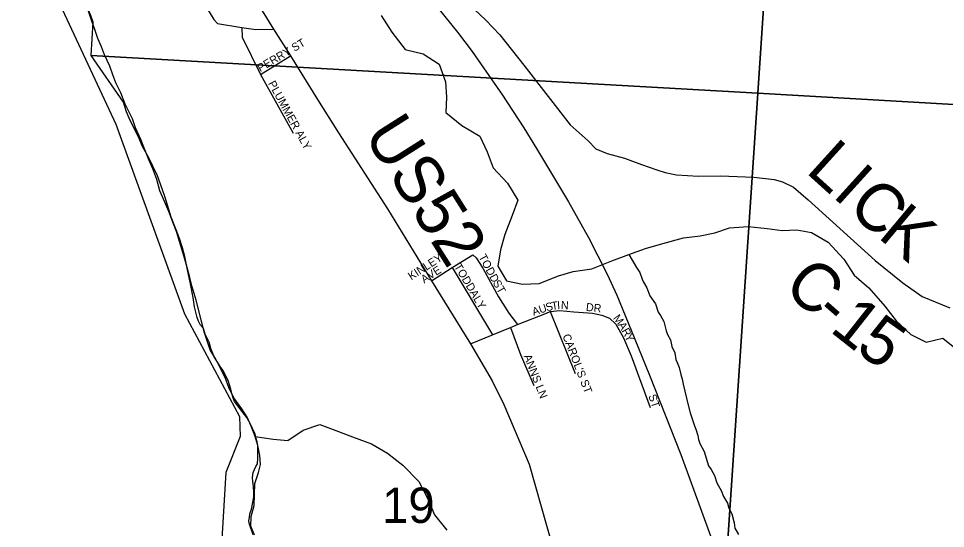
# Model space of a CAD drawing. Extents: x 1949938.81 to 1949945.61, y 152207.65 to 152214.09.
# Drawn here: x 1949939.486 to 1949940.583, y 152211.771 to 152212.375 of the extents above; entities that cross this region are included whole.
import ezdxf

# ---------------------------------------------------------------- set-up
doc = ezdxf.new("R2010")
doc.units = 0
for name, color, linetype in [('GM_X_County', 7, 'Continuous'), ('GM_X_County_Road', 7, 'Continuous'), ('GM_X_County_Road_Text', 7, 'Continuous'), ('GM_X_Major_River', 7, 'Continuous'), ('GM_X_Minor_River', 7, 'Continuous'), ('GM_X_Section', 7, 'Continuous'), ('GM_X_Section_Text', 7, 'Continuous'), ('GM_X_Township', 7, 'Continuous'), ('GM_X_Township_Subdivision', 7, 'Continuous'), ('GM_X_Township_Subdivision_Text', 7, 'Continuous'), ('GM_X_US_Route', 7, 'Continuous')]:
    doc.layers.add(name, color=color, linetype=linetype)

msp = doc.modelspace()

# ---------------------------------------------------------------- linework, layer by layer
at = {"layer": 'GM_X_County'}
msp.add_lwpolyline([(1949938.8069, 152213.1813), (1949938.8908, 152213.14), (1949939.0267, 152213.041), (1949939.1111, 152212.9977), (1949939.166, 152212.9381), (1949939.244, 152212.8721), (1949939.3272, 152212.7909), (1949939.4464, 152212.5807), (1949939.6012, 152212.2498), (1949939.6822, 152212.0255), (1949939.7473, 152211.904), (1949939.7481, 152211.8801), (1949939.7311, 152211.8376), (1949939.7258, 152211.7457)], dxfattribs=at)
at = {"layer": 'GM_X_County_Road'}
for points in [[(1949939.6083, 152212.6496), (1949939.6416, 152212.5985), (1949939.7012, 152212.4996), (1949939.734, 152212.4495), (1949939.7877, 152212.362), (1949939.8079, 152212.3305), (1949939.8398, 152212.2788), (1949939.8646, 152212.2394), (1949939.9224, 152212.1496), (1949939.9746, 152212.0644), (1949940.0209, 152211.9898), (1949940.0463, 152211.946), (1949940.0603, 152211.9182), (1949940.0902, 152211.8474), (1949940.1245, 152211.7264)], [(1949939.9911, 152212.4181), (1949940.0391, 152212.3728), (1949940.0554, 152212.3554), (1949940.084, 152212.3196), (1949940.1389, 152212.2489), (1949940.16, 152212.2301), (1949940.1692, 152212.2206), (1949940.1827, 152212.215), (1949940.2031, 152212.2094), (1949940.2232, 152212.202), (1949940.2415, 152212.1957), (1949940.2514, 152212.1925), (1949940.2645, 152212.19), (1949940.2905, 152212.1882), (1949940.3166, 152212.1886), (1949940.3563, 152212.187), (1949940.3803, 152212.1844), (1949940.39, 152212.1815), (1949940.403, 152212.1752), (1949940.4203, 152212.1604), (1949940.4996, 152212.0883), (1949940.5324, 152212.0621), (1949940.5553, 152212.0457), (1949940.588, 152212.0326)]]:
    msp.add_lwpolyline(points, dxfattribs=at)
at = {"layer": 'GM_X_Major_River'}
for points in [[(1949939.5841, 152212.3413), (1949939.5799, 152212.3512), (1949939.5765, 152212.3607), (1949939.5723, 152212.3728), (1949939.5682, 152212.3846), (1949939.5644, 152212.3971), (1949939.5595, 152212.4115), (1949939.5534, 152212.427), (1949939.5485, 152212.438), (1949939.544, 152212.4483), (1949939.5391, 152212.4589), (1949939.5345, 152212.4699), (1949939.53, 152212.4802), (1949939.5251, 152212.4904), (1949939.5191, 152212.5029), (1949939.5138, 152212.5128), (1949939.5089, 152212.5234), (1949939.5028, 152212.5336), (1949939.4986, 152212.5431), (1949939.4907, 152212.5556), (1949939.4835, 152212.5689)], [(1949939.765, 152211.7635), (1949939.7609, 152211.7741), (1949939.7613, 152211.7855), (1949939.7647, 152211.7988), (1949939.7654, 152211.8246), (1949939.77, 152211.8378), (1949939.7722, 152211.8473), (1949939.7715, 152211.8576), (1949939.7692, 152211.8697), (1949939.7658, 152211.8803), (1949939.7613, 152211.8925), (1949939.7564, 152211.9031), (1949939.7503, 152211.913), (1949939.7409, 152211.9259), (1949939.7348, 152211.9384), (1949939.7303, 152211.9502), (1949939.7246, 152211.9615), (1949939.7193, 152211.9718), (1949939.7129, 152211.9828), (1949939.7095, 152211.9923), (1949939.7061, 152212.0029), (1949939.7023, 152212.0162), (1949939.6997, 152212.0276), (1949939.6963, 152212.0416), (1949939.6914, 152212.0572), (1949939.6887, 152212.0685), (1949939.6853, 152212.0803), (1949939.6827, 152212.0902), (1949939.6797, 152212.1008), (1949939.6766, 152212.111), (1949939.6729, 152212.1228), (1949939.6687, 152212.1338), (1949939.6638, 152212.1463), (1949939.6589, 152212.1573), (1949939.6532, 152212.171), (1949939.6494, 152212.1843), (1949939.6449, 152212.1968), (1949939.6407, 152212.2066), (1949939.6351, 152212.2207), (1949939.6305, 152212.2317), (1949939.6245, 152212.2453), (1949939.6207, 152212.256), (1949939.612, 152212.2734), (1949939.6071, 152212.2867), (1949939.6011, 152212.2988), (1949939.5977, 152212.3083), (1949939.5939, 152212.3182), (1949939.5875, 152212.3318), (1949939.5841, 152212.3413)]]:
    msp.add_lwpolyline(points, dxfattribs=at)
at = {"layer": 'GM_X_Minor_River'}
for points in [[(1949939.9149, 152212.3785), (1949939.9277, 152212.3587), (1949939.9436, 152212.3382), (1949939.9647, 152212.3328), (1949939.9836, 152212.3206), (1949939.9911, 152212.3), (1949939.9925, 152212.2818), (1949939.9917, 152212.2636), (1949940.0106, 152212.2483), (1949940.0317, 152212.2354), (1949940.0407, 152212.2171), (1949940.0475, 152212.1981), (1949940.0648, 152212.1798), (1949940.0769, 152212.16), (1949940.07, 152212.1418), (1949940.0615, 152212.1191), (1949940.0562, 152212.1009), (1949940.0531, 152212.0819), (1949940.0636, 152212.0644), (1949940.0825, 152212.0605), (1949940.1022, 152212.0612), (1949940.125, 152212.0702), (1949940.1424, 152212.0755), (1949940.1644, 152212.0785), (1949940.1879, 152212.0882), (1949940.2084, 152212.0957), (1949940.2281, 152212.1025), (1949940.2486, 152212.1085), (1949940.2728, 152212.1152), (1949940.2925, 152212.1175), (1949940.31, 152212.1212), (1949940.3274, 152212.1272), (1949940.3494, 152212.1286), (1949940.3721, 152212.1263), (1949940.3895, 152212.1239), (1949940.4069, 152212.1246), (1949940.4243, 152212.1215), (1949940.444, 152212.11), (1949940.4628, 152212.0902), (1949940.4749, 152212.0712), (1949940.4922, 152212.056), (1949940.5111, 152212.0346), (1949940.5246, 152212.0171), (1949940.542, 152212.0011), (1949940.5601, 152211.9919), (1949940.5798, 152211.9964), (1949940.5979, 152211.9819)], [(1949940.2084, 152212.0957), (1949940.2173, 152212.08), (1949940.2214, 152212.0742), (1949940.2239, 152212.0662), (1949940.2257, 152212.0628), (1949940.2294, 152212.0563), (1949940.233, 152212.0467), (1949940.2396, 152212.0371), (1949940.2429, 152212.0275), (1949940.2455, 152212.0233), (1949940.2495, 152212.0164), (1949940.2523, 152212.0053), (1949940.2541, 152212.0008), (1949940.2575, 152211.9946), (1949940.2592, 152211.9866), (1949940.2625, 152211.9793), (1949940.2639, 152211.9713), (1949940.2653, 152211.9679), (1949940.2679, 152211.9618), (1949940.2696, 152211.9538), (1949940.2714, 152211.948), (1949940.2724, 152211.9423), (1949940.2763, 152211.9256), (1949940.2774, 152211.9221), (1949940.2809, 152211.9084), (1949940.2824, 152211.9034), (1949940.286, 152211.8927), (1949940.2874, 152211.8889), (1949940.2899, 152211.8816), (1949940.2906, 152211.8767), (1949940.2924, 152211.8721), (1949940.2972, 152211.8625), (1949940.3026, 152211.8457), (1949940.3055, 152211.8411), (1949940.3095, 152211.8342), (1949940.3124, 152211.8254), (1949940.3143, 152211.822), (1949940.3176, 152211.8162), (1949940.3201, 152211.8093), (1949940.3249, 152211.8013), (1949940.3267, 152211.7955), (1949940.33, 152211.7886), (1949940.3328, 152211.778), (1949940.3338, 152211.7719), (1949940.3382, 152211.7642)], [(1949939.7658, 152211.8803), (1949939.7871, 152211.8771), (1949939.8045, 152211.8755), (1949939.8228, 152211.8876), (1949939.8425, 152211.8944), (1949939.8614, 152211.8875), (1949939.881, 152211.8798), (1949939.9037, 152211.8714), (1949939.9226, 152211.8607), (1949939.9407, 152211.8462), (1949939.9596, 152211.8271), (1949939.9701, 152211.8073), (1949939.9784, 152211.7876), (1949939.9927, 152211.7693)]]:
    msp.add_lwpolyline(points, dxfattribs=at)
at = {"layer": 'GM_X_Section'}
for points in [[(1949940.4294, 152213.3146), (1949940.3609, 152212.2864), (1949939.5717, 152212.3312), (1949939.5744, 152212.3703), (1949939.5718, 152212.3771), (1949939.5691, 152212.3839), (1949939.5646, 152212.393), (1949939.5608, 152212.4021), (1949939.5544, 152212.4169), (1949939.5517, 152212.4267), (1949939.5472, 152212.4392), (1949939.5434, 152212.451), (1949939.5392, 152212.4624), (1949939.5332, 152212.476), (1949939.526, 152212.4908), (1949939.5139, 152212.5139), (1949939.5052, 152212.531), (1949939.5018, 152212.5385), (1949939.4938, 152212.5518), (1949939.4832, 152212.5689)], [(1949939.7635, 152211.7639), (1949939.7589, 152211.7776), (1949939.7585, 152211.7806), (1949939.7593, 152211.7844), (1949939.7597, 152211.7886), (1949939.7616, 152211.7943), (1949939.7631, 152211.8022), (1949939.7642, 152211.809), (1949939.7642, 152211.8136), (1949939.7639, 152211.8211), (1949939.7631, 152211.8272), (1949939.7627, 152211.8318), (1949939.7635, 152211.8378), (1949939.7669, 152211.8446), (1949939.7688, 152211.848), (1949939.7692, 152211.8545), (1949939.7692, 152211.8617), (1949939.7692, 152211.8689), (1949939.7684, 152211.8738), (1949939.7673, 152211.878), (1949939.7658, 152211.8829), (1949939.7601, 152211.8958), (1949939.756, 152211.9026), (1949939.7507, 152211.9098), (1949939.7454, 152211.9166), (1949939.7416, 152211.9216), (1949939.7397, 152211.9269), (1949939.737, 152211.9363), (1949939.734, 152211.9466), (1949939.7306, 152211.9534), (1949939.728, 152211.9583), (1949939.7246, 152211.9629), (1949939.7212, 152211.9682), (1949939.7174, 152211.9746), (1949939.7136, 152211.9845), (1949939.7121, 152211.9909), (1949939.7068, 152212.0015), (1949939.7049, 152212.008), (1949939.7011, 152212.0121), (1949939.6988, 152212.0167), (1949939.6973, 152212.0209), (1949939.6943, 152212.0337), (1949939.6924, 152212.0447), (1949939.6894, 152212.0607), (1949939.686, 152212.0773), (1949939.6826, 152212.0932), (1949939.6799, 152212.1035), (1949939.6765, 152212.1145), (1949939.6724, 152212.1247), (1949939.6667, 152212.1399), (1949939.6595, 152212.163), (1949939.6561, 152212.1732), (1949939.6505, 152212.1887), (1949939.6448, 152212.2001), (1949939.6402, 152212.21), (1949939.6327, 152212.2232), (1949939.6274, 152212.2354), (1949939.6217, 152212.2471), (1949939.6168, 152212.257), (1949939.6137, 152212.2645), (1949939.6115, 152212.2717), (1949939.61, 152212.2759), (1949939.5717, 152212.3312), (1949940.3609, 152212.2864), (1949940.2943, 152211.2945)]]:
    msp.add_lwpolyline(points, dxfattribs=at)
for points in [[(1949941.5133, 152213.2491), (1949941.4524, 152212.2232), (1949940.3609, 152212.2864), (1949940.4294, 152213.3146)], [(1949940.3609, 152212.2864), (1949941.4524, 152212.2232), (1949941.3926, 152211.2226), (1949940.2943, 152211.2945)]]:
    msp.add_lwpolyline(points, close=True, dxfattribs=at)
at = {"layer": 'GM_X_Township'}
msp.add_lwpolyline([(1949938.8069, 152213.1813), (1949938.8908, 152213.14), (1949939.0267, 152213.041), (1949939.1111, 152212.9977), (1949939.166, 152212.9381), (1949939.244, 152212.8721), (1949939.3272, 152212.7909), (1949939.4464, 152212.5807), (1949939.6012, 152212.2498), (1949939.6822, 152212.0255), (1949939.7473, 152211.904), (1949939.7481, 152211.8801), (1949939.7311, 152211.8376), (1949939.7258, 152211.7457)], dxfattribs=at)
at = {"layer": 'GM_X_Township_Subdivision'}
for points in [[(1949939.5935, 152212.5526), (1949939.6126, 152212.5382), (1949939.6283, 152212.514), (1949939.6392, 152212.4996), (1949939.6473, 152212.4901), (1949939.6559, 152212.4742), (1949939.6666, 152212.4544), (1949939.6776, 152212.4365), (1949939.7049, 152212.3939), (1949939.7169, 152212.3737), (1949939.7214, 152212.3689), (1949939.7501, 152212.3643), (1949939.7668, 152212.3617), (1949939.7877, 152212.362)], [(1949939.7501, 152212.3643), (1949939.7506, 152212.3527), (1949939.7724, 152212.3086), (1949939.811, 152212.239)], [(1949939.7724, 152212.3086), (1949939.8079, 152212.3305)], [(1949939.9746, 152212.0644), (1949939.999, 152212.08), (1949940.0236, 152212.0953)], [(1949940.0236, 152212.0953), (1949940.0276, 152212.0916), (1949940.0355, 152212.0795), (1949940.0538, 152212.0453), (1949940.0662, 152212.0263), (1949940.0764, 152212.0128)], [(1949939.999, 152212.08), (1949940.0469, 152212.0007)], [(1949940.0209, 152211.9898), (1949940.0469, 152212.0007), (1949940.068, 152212.0094), (1949940.0764, 152212.0128), (1949940.1107, 152212.0263), (1949940.1153, 152212.0281), (1949940.1266, 152212.0293), (1949940.1431, 152212.0279), (1949940.1653, 152212.0262), (1949940.1764, 152212.0238)], [(1949940.1153, 152212.0281), (1949940.1447, 152211.9547)], [(1949940.1764, 152212.0238), (1949940.1855, 152212.0203), (1949940.1928, 152212.0133), (1949940.2019, 152211.9969), (1949940.211, 152211.9758), (1949940.2336, 152211.9147)], [(1949940.068, 152212.0094), (1949940.08, 152211.9774), (1949940.0956, 152211.9405)]]:
    msp.add_lwpolyline(points, dxfattribs=at)
at = {"layer": 'GM_X_US_Route'}
for points in [[(1949939.5633, 152212.7584), (1949939.5712, 152212.7524), (1949939.6236, 152212.7189), (1949939.7271, 152212.6418), (1949939.8216, 152212.5586), (1949939.9015, 152212.4802), (1949939.9335, 152212.446), (1949939.9688, 152212.4043), (1949940.0056, 152212.3587), (1949940.0227, 152212.3356), (1949940.0559, 152212.2881)], [(1949940.0559, 152212.2881), (1949940.0578, 152212.2854), (1949940.084, 152212.2453), (1949940.0988, 152212.2209)], [(1949940.0988, 152212.2209), (1949940.137, 152212.1578), (1949940.1603, 152212.1157), (1949940.1824, 152212.0725), (1949940.1941, 152212.0476), (1949940.211, 152212.006), (1949940.2326, 152211.9527), (1949940.2697, 152211.8588), (1949940.3524, 152211.6329), (1949940.4147, 152211.4664), (1949940.448, 152211.375)]]:
    msp.add_lwpolyline(points, dxfattribs=at)

# ---------------------------------------------------------------- texts
at = {"layer": 'GM_X_County_Road_Text'}
for s, height, rotation, p in [('US52', 0.05682, 302.3564, (1949939.8933, 152212.2375)), ('L', 0.0568, 317.8303, (1949940.4163, 152212.1935)), ('I', 0.0568, 317.8278, (1949940.4478, 152212.1649)), ('C', 0.0568, 317.9398, (1949940.4652, 152212.1492)), ('K', 0.0568, 320.1175, (1949940.5016, 152212.1164)), ('C', 0.0568, 317.4459, (1949940.3892, 152212.0554)), ('-', 0.0568, 318.8513, (1949940.4247, 152212.0228)), ('1', 0.0568, 321.7372, (1949940.4447, 152212.0055)), ('5', 0.0568, 324.7667, (1949940.4748, 152211.9818))]:
    msp.add_text(s, height=height, rotation=rotation, dxfattribs=at).set_placement(p)
at = {"layer": 'GM_X_Section_Text'}
msp.add_text('19', height=0.04186, rotation=0, dxfattribs=at).set_placement((1949939.9161, 152211.778))
at = {"layer": 'GM_X_Township_Subdivision_Text'}
for s, rotation, p in [('PERRY ST', 30.6503, (1949939.7719, 152212.3112)), ('PLUMMER ALY', 298.8353, (1949939.781, 152212.298)), ('KINLEY', 32.8004, (1949939.9507, 152212.0649)), ('TODD', 297.899, (1949940.0302, 152212.093)), ('AVE', 32.6173, (1949939.9659, 152212.0612)), ('TODD', 301.219, (1949940.001, 152212.0814)), ('ST', 299.7432, (1949940.0468, 152212.0622)), ('ALY', 300.9626, (1949940.0193, 152212.0505)), ('U', 18.5965, (1949940.1034, 152212.0256)), ('S', 14.9673, (1949940.1111, 152212.0282)), ('T', 8.2262, (1949940.1173, 152212.0299)), ('I', 4.4951, (1949940.1237, 152212.0308)), ('N', 357.0781, (1949940.1276, 152212.0312)), ('DR', 353.9898, (1949940.1571, 152212.0289)), ('A', 18.5965, (1949940.0955, 152212.023)), ('M', 307.7979, (1949940.1891, 152212.0201)), ('A', 300.9188, (1949940.195, 152212.0124)), ('R', 299.3382, (1949940.1993, 152212.0053)), ('Y', 295.8479, (1949940.2029, 152211.9989)), ("CAROL'S ST", 291.2504, (1949940.1295, 152211.9994)), ('ANNS LN', 291.4506, (1949940.0836, 152211.9753)), ('ST', 288.4382, (1949940.2312, 152211.9285))]:
    msp.add_text(s, height=0.00947, rotation=rotation, dxfattribs=at).set_placement(p)

doc.saveas('drawing.dxf')
